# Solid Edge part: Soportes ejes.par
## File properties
Author: there
Template: iso metric part.par
Last saved by: there
Revision: 10
Application: Solid Edge
Precisión: 0.990
Username: there
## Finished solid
Body 1: solid body, 23 faces, 62 edges, 40 vertices.
  Faces by surface: plane 21, cylinder 2
  Edges by curve: line 58, circle 4
Bounding box of the edges (mm): 43.000 x 3.000 x 30.000, from (-25, -3, -15) to (18, 0, 15).
Cylindrical faces by radius (mm): R3.2 x1, R15 x1
Planar faces by outward normal: +x 7, +y 1, +z 5, -x 2, -y 1, -z 5
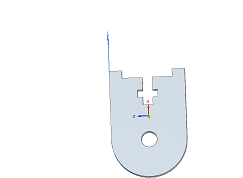
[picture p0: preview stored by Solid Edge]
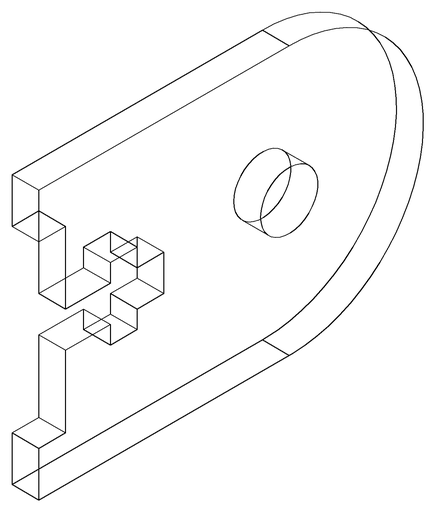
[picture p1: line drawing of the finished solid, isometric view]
